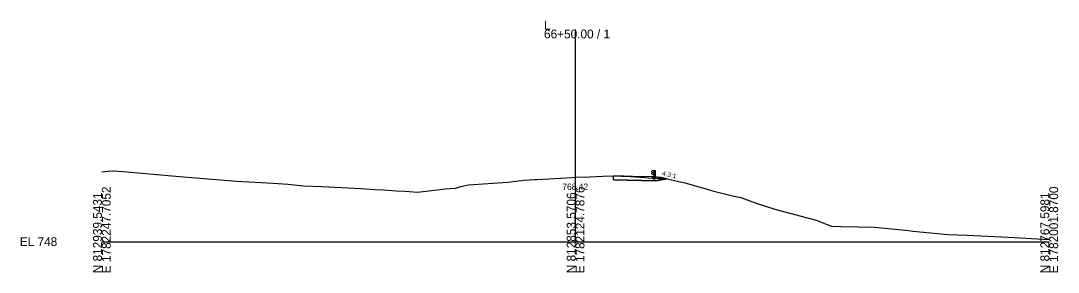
# Model space of a CAD drawing. Extents: x -26 to 7903, y -10 to 9573.
# Drawn here: x 2974.3 to 3302.8, y 7490.3 to 7570 of the extents above; entities that cross this region are included whole.
import ezdxf

# ---------------------------------------------------------------- set-up
doc = ezdxf.new("R2010")
doc.units = 0
for name, color, linetype in [('Exist Cross Section Cell', 7, 'Continuous'), ('Exist XS Center Line Elevation Label', 7, 'Continuous'), ('Exist XS Ground Line', 7, 'Continuous'), ('Prop XS Earthwork Shape', 7, 'Continuous'), ('Prop XS Finish Grade', 7, 'Continuous'), ('Prop XS Finish Grade Paved Shoulder', 7, 'Continuous'), ('Prop XS Guardrail', 7, 'Continuous'), ('Prop XS Pvmt Edge Slope', 7, 'Continuous'), ('Prop XS Side Slope Text', 7, 'Continuous'), ('Prop XS Subgrade Earthwork', 7, 'Continuous'), ('Scratch_Level_3', 7, 'Continuous'), ('Scratch_Level_6', 7, 'Continuous')]:
    doc.layers.add(name, color=color, linetype=linetype)

msp = doc.modelspace()

# ---------------------------------------------------------------- linework, layer by layer
at = {"layer": 'Exist Cross Section Cell'}
for p, q in [((3150, 7500), (3150, 7567.24)), ((3000, 7500), (3150, 7500)), ((3150, 7500), (3300, 7500))]:
    msp.add_line(p, q, dxfattribs=at)
at = {"layer": 'Exist XS Ground Line'}
for p, q in [((3000, 7522.11), (3001.96, 7522.32)), ((3001.96, 7522.32), (3003.85, 7522.41)), ((3003.85, 7522.41), (3008.04, 7522.11)), ((3008.04, 7522.11), (3016.29, 7521.35)), ((3016.29, 7521.35), (3024.54, 7520.7)), ((3024.54, 7520.7), (3042.7, 7519.2)), ((3137.77, 7519.76), (3149.07, 7520.38)), ((3149.07, 7520.38), (3150, 7520.42)), ((3150, 7520.42), (3154.38, 7520.6)), ((3154.38, 7520.6), (3160.75, 7520.86)), ((3160.75, 7520.86), (3164.59, 7520.82)), ((3164.59, 7520.82), (3165.61, 7520.75)), ((3165.61, 7520.75), (3170.52, 7520.42)), ((3170.52, 7520.42), (3174.34, 7520.13)), ((3174.34, 7520.13), (3176.11, 7520.01)), ((3042.7, 7519.2), (3054.26, 7518.51)), ((3054.26, 7518.51), (3058.89, 7518.24)), ((3058.89, 7518.24), (3063.79, 7517.75)), ((3063.79, 7517.75), (3069.64, 7517.49)), ((3069.64, 7517.49), (3082.08, 7516.83)), ((3082.08, 7516.83), (3086.3, 7516.59)), ((3108.58, 7516.75), (3112.02, 7516.98)), ((3112.02, 7516.98), (3113.67, 7517.46)), ((3113.67, 7517.46), (3116.13, 7517.99)), ((3116.13, 7517.99), (3128.54, 7518.89)), ((3128.54, 7518.89), (3129.3, 7518.96)), ((3129.3, 7518.96), (3132.86, 7519.41)), ((3132.86, 7519.41), (3133.74, 7519.5)), ((3133.74, 7519.5), (3137.06, 7519.71)), ((3137.06, 7519.71), (3137.77, 7519.76)), ((3176.11, 7520.01), (3176.74, 7519.99)), ((3176.74, 7519.99), (3179.05, 7519.88)), ((3179.05, 7519.88), (3184.62, 7518.69)), ((3184.62, 7518.69), (3190.14, 7517.1)), ((3190.14, 7517.1), (3193.4, 7516.17)), ((3086.3, 7516.59), (3089.16, 7516.39)), ((3089.16, 7516.39), (3093.22, 7516.15)), ((3093.22, 7516.15), (3095.88, 7516.01)), ((3095.88, 7516.01), (3097.3, 7515.92)), ((3097.3, 7515.92), (3099.91, 7515.7)), ((3099.91, 7515.7), (3107.98, 7516.7)), ((3107.98, 7516.7), (3108.58, 7516.75)), ((3193.4, 7516.17), (3199.71, 7514.58)), ((3199.71, 7514.58), (3202.37, 7513.96)), ((3202.37, 7513.96), (3207.22, 7512.18)), ((3207.22, 7512.18), (3213.1, 7510.26)), ((3213.1, 7510.26), (3224.55, 7507.26)), ((3224.55, 7507.26), (3225.45, 7507)), ((3225.45, 7507), (3226.5, 7506.71)), ((3226.5, 7506.71), (3228.29, 7505.97)), ((3228.29, 7505.97), (3231.04, 7504.97)), ((3231.04, 7504.97), (3234.14, 7504.83)), ((3234.14, 7504.83), (3244.65, 7504.62)), ((3244.65, 7504.62), (3255.38, 7503.51)), ((3255.38, 7503.51), (3256.77, 7503.38)), ((3256.77, 7503.38), (3268.01, 7502.29)), ((3268.01, 7502.29), (3273.97, 7502.04)), ((3273.97, 7502.04), (3280.68, 7501.76)), ((3280.68, 7501.76), (3287.01, 7501.48)), ((3287.01, 7501.48), (3300, 7500.72))]:
    msp.add_line(p, q, dxfattribs=at)
at = {"layer": 'Prop XS Earthwork Shape'}
msp.add_lwpolyline([(3162, 7520.85), (3164.59, 7520.82), (3165.61, 7520.75), (3170.52, 7520.42), (3174.34, 7520.13), (3176.11, 7520.01), (3176.74, 7519.99), (3179.05, 7519.88), (3175.28, 7519.33), (3162, 7519.6)], close=True, dxfattribs=at)
at = {"layer": 'Prop XS Finish Grade'}
for p, q in [((3174, 7520.61), (3177, 7520.37)), ((3177, 7520.37), (3179.05, 7519.88))]:
    msp.add_line(p, q, dxfattribs=at)
at = {"layer": 'Prop XS Finish Grade Paved Shoulder'}
msp.add_line((3162, 7520.85), (3174, 7520.61), dxfattribs=at)
at = {"layer": 'Prop XS Guardrail'}
for p, q in [((3174.03, 7522.28), (3174, 7522.22)), ((3174, 7522.22), (3174.03, 7522.16)), ((3174.03, 7521.67), (3174, 7521.61)), ((3174, 7521.61), (3174.03, 7521.55)), ((3174.32, 7522.48), (3174.03, 7522.28)), ((3174.03, 7522.16), (3174.32, 7521.96)), ((3174.32, 7521.87), (3174.03, 7521.67)), ((3174.03, 7521.55), (3174.32, 7521.35)), ((3174.82, 7522.48), (3174.32, 7522.48)), ((3174.32, 7521.96), (3174.32, 7521.87)), ((3174.32, 7521.35), (3174.82, 7521.35)), ((3175.32, 7522.48), (3174.82, 7522.48)), ((3174.82, 7522.48), (3174.82, 7519.98)), ((3175.32, 7519.98), (3175.32, 7522.48))]:
    msp.add_line(p, q, dxfattribs=at)
at = {"layer": 'Prop XS Pvmt Edge Slope'}
msp.add_line((3174, 7520.61), (3175.28, 7519.33), dxfattribs=at)
at = {"layer": 'Prop XS Subgrade Earthwork'}
for p, q in [((3162, 7519.6), (3162, 7520.85)), ((3162, 7519.6), (3175.28, 7519.33)), ((3175.28, 7519.33), (3179.05, 7519.88))]:
    msp.add_line(p, q, dxfattribs=at)
at = {"layer": 'Scratch_Level_3'}
for p, q in [((3177, 7520.37), (3174, 7520.61)), ((3174, 7520.61), (3175.28, 7519.33)), ((3179.05, 7519.88), (3177, 7520.37)), ((3175.28, 7519.33), (3179.05, 7519.88))]:
    msp.add_line(p, q, dxfattribs=at)
at = {"layer": 'Scratch_Level_6'}
for points in [[(3162, 7520.85), (3164.59, 7520.82), (3165.13, 7520.78)], [(3162, 7519.6), (3162, 7520.85), (3165.13, 7520.78), (3165.61, 7520.75), (3170.52, 7520.42), (3174.34, 7520.13), (3176.11, 7520.01), (3176.74, 7519.99), (3179.05, 7519.88), (3175.28, 7519.33)]]:
    msp.add_lwpolyline(points, close=True, dxfattribs=at)

# ---------------------------------------------------------------- texts
at = {"layer": 'Exist Cross Section Cell'}
for s, p in [('L', (3140, 7567.24)), ('66+50.00 / 1', (3140, 7564.44)), ('EL 748', (2974, 7498.6))]:
    msp.add_text(s, height=2.8, dxfattribs=at).set_placement(p)
for s, p in [('E 1782247.7052', (3002.8, 7490)), ('E 1782124.7876', (3152.8, 7490)), ('E 1782001.8700', (3302.8, 7490)), ('N 812939.5431', (3000, 7490)), ('N 812853.5706', (3150, 7490)), ('N 812767.5981', (3300, 7490))]:
    msp.add_text(s, height=2.8, rotation=90, dxfattribs=at).set_placement(p)
at = {"layer": 'Exist XS Center Line Elevation Label'}
msp.add_text('768.42', height=2, dxfattribs=at).set_placement((3145.79, 7516.42))
at = {"layer": 'Prop XS Side Slope Text'}
msp.add_text('4.3:1', height=1.5, rotation=346.7644, dxfattribs=at).set_placement((3177.26, 7521.06))

doc.saveas('drawing.dxf')
